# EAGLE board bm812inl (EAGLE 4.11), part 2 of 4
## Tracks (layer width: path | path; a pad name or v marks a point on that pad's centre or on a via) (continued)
D03MA4L  (via drill 0.61) (continued)
  Bottom 0.254: v102.91,115.24 102.59,115.56 98.46,115.56 97.83,116.19 88.94,116.19 88.3,115.56 82.59,115.56 81.63,114.61 C15.L1 | 104.81,195.57 95.29,195.57 94.33,196.52 B14.D1 | 104.81,195.57 105.76,196.52 B13.D1 | 117.51,195.57 118.46,196.52 B12.D1 | 104.81,195.57 117.51,195.57 | 130.21,195.57 131.16,196.52 B11.D1 | 117.51,195.57 130.21,195.57 | 142.91,195.57 143.86,196.52 B10.D1 | 130.21,195.57 142.91,195.57 | 155.61,195.57 156.56,196.52 B09.D1 | 142.91,195.57 155.61,195.57 | 168.31,195.57 169.26,196.52 B08.D1 | 155.61,195.57 168.31,195.57 | 181.01,195.57 181.96,196.52 B07.D1 | 168.31,195.57 181.01,195.57 | 193.71,195.57 194.66,196.52 B06.D1 | 181.01,195.57 193.71,195.57 | 206.41,195.57 207.36,196.52 B05.D1 | 193.71,195.57 206.41,195.57 | 219.11,195.57 220.06,196.52 B04.D1 | 206.41,195.57 219.11,195.57 | 231.81,195.57 232.76,196.52 B03.D1 | 219.11,195.57 231.81,195.57 | 244.51,195.57 245.46,196.52 B02.D1 | 231.81,195.57 244.51,195.57 | 244.51,195.57 257.21,195.57 258.16,196.52 B01.D1
D03MA5L  (via drill 0.61)
  Top 0.254: v102.91,96.19 105.13,98.41 105.13,187.31 109.26,191.44 109.26,193.03 B13.E1
  Bottom 0.254: v102.91,96.19 102.59,96.51 98.46,96.51 97.83,97.14 85.76,97.14 84.81,98.1 C15.S1 | 107.99,192.39 98.46,192.39 97.51,193.34 B14.E1 | 107.99,192.39 108.94,193.34 B13.E1 | 120.69,192.39 121.64,193.34 B12.E1 | 107.99,192.39 120.69,192.39 | 133.39,192.39 134.34,193.34 B11.E1 | 120.69,192.39 133.39,192.39 | 146.09,192.39 147.04,193.34 B10.E1 | 133.39,192.39 146.09,192.39 | 158.79,192.39 159.74,193.34 B09.E1 | 146.09,192.39 158.79,192.39 | 171.49,192.39 172.44,193.34 B08.E1 | 158.79,192.39 171.49,192.39 | 184.19,192.39 185.14,193.34 B07.E1 | 171.49,192.39 184.19,192.39 | 196.89,192.39 197.84,193.34 B06.E1 | 184.19,192.39 196.89,192.39 | 209.59,192.39 210.54,193.34 B05.E1 | 196.89,192.39 209.59,192.39 | 222.29,192.39 223.24,193.34 B04.E1 | 209.59,192.39 222.29,192.39 | 234.99,192.39 235.94,193.34 B03.E1 | 222.29,192.39 234.99,192.39 | 247.69,192.39 248.64,193.34 B02.E1 | 234.99,192.39 247.69,192.39 | 247.69,192.39 260.39,192.39 261.34,193.34 B01.E1
D03MA6L  (via drill 0.61)
  Top 0.254: v93.38,124.13 94.97,125.72 94.97,185.09 96.56,186.68 B14.H1
  Bottom 0.254: v93.38,124.13 91.79,122.54 76.87,122.54 75.28,120.96 C15.J2 | 111.16,186.04 110.21,186.99 B13.H1 | 111.16,186.04 120.69,186.04 | 120.69,186.04 121.64,186.99 B12.H1 | 133.39,186.04 134.34,186.99 B11.H1 | 120.69,186.04 133.39,186.04 | 146.09,186.04 147.04,186.99 B10.H1 | 133.39,186.04 146.09,186.04 | 158.79,186.04 159.74,186.99 B09.H1 | 146.09,186.04 158.79,186.04 | 171.49,186.04 172.44,186.99 B08.H1 | 158.79,186.04 171.49,186.04 | 184.19,186.04 185.14,186.99 B07.H1 | 171.49,186.04 184.19,186.04 | 196.89,186.04 197.84,186.99 B06.H1 | 184.19,186.04 196.89,186.04 | 209.59,186.04 210.54,186.99 B05.H1 | 196.89,186.04 209.59,186.04 | 222.29,186.04 223.24,186.99 B04.H1 | 209.59,186.04 222.29,186.04 | 234.99,186.04 235.94,186.99 B03.H1 | 222.29,186.04 234.99,186.04 | 247.69,186.04 248.64,186.99 B02.H1 | 234.99,186.04 247.69,186.04 | 247.69,186.04 260.39,186.04 261.34,186.99 B01.H1 | 111.16,186.04 102.59,186.04 101.95,186.68 97.83,186.68 97.51,186.99 B14.H1
D03MA7L  (via drill 0.61)
  Top 0.254: v88.62,106.03 88.62,170.17 92.43,173.98 92.43,182.55 93.38,183.5 B14.J1
  Bottom 0.254: v88.62,106.03 79.41,106.03 78.46,105.08 C15.P2 | 104.81,182.87 105.76,183.82 B13.J1 | 104.81,182.87 95.29,182.87 94.33,183.82 B14.J1 | 117.51,182.87 118.46,183.82 B12.J1 | 104.81,182.87 117.51,182.87 | 130.21,182.87 131.16,183.82 B11.J1 | 117.51,182.87 130.21,182.87 | 142.91,182.87 143.86,183.82 B10.J1 | 130.21,182.87 142.91,182.87 | 155.61,182.87 156.56,183.82 B09.J1 | 142.91,182.87 155.61,182.87 | 168.31,182.87 169.26,183.82 B08.J1 | 155.61,182.87 168.31,182.87 | 181.01,182.87 181.96,183.82 B07.J1 | 168.31,182.87 181.01,182.87 | 193.71,182.87 194.66,183.82 B06.J1 | 181.01,182.87 193.71,182.87 | 206.41,182.87 207.36,183.82 B05.J1 | 193.71,182.87 206.41,182.87 | 219.11,182.87 220.06,183.82 B04.J1 | 206.41,182.87 219.11,182.87 | 231.81,182.87 232.76,183.82 B03.J1 | 219.11,182.87 231.81,182.87 | 244.51,182.87 245.46,183.82 B02.J1 | 231.81,182.87 244.51,182.87 | 244.51,182.87 257.21,182.87 258.16,183.82 B01.J1
D03MA8L  (via drill 0.61)
  Top 0.254: v90.21,87.3 91.79,85.71 91.79,65.71 93.38,64.12 D14.D1
  Bottom 0.254: 104.81,62.22 95.29,62.22 94.33,63.17 D14.D1 | 104.81,62.22 105.76,63.17 D13.D1 | 117.51,62.22 118.46,63.17 D12.D1 | 117.51,62.22 104.81,62.22 | 130.21,62.22 131.16,63.17 D11.D1 | 130.21,62.22 117.51,62.22 | 142.91,62.22 143.86,63.17 D10.D1 | 142.91,62.22 130.21,62.22 | 155.61,62.22 156.56,63.17 D09.D1 | 155.61,62.22 142.91,62.22 | 168.31,62.22 169.26,63.17 D08.D1 | 168.31,62.22 155.61,62.22 | 181.01,62.22 181.96,63.17 D07.D1 | 181.01,62.22 168.31,62.22 | 193.71,62.22 194.66,63.17 D06.D1 | 193.71,62.22 181.01,62.22 | 206.41,62.22 207.36,63.17 D05.D1 | 193.71,62.22 206.41,62.22 | 219.11,62.22 220.06,63.17 D04.D1 | 206.41,62.22 219.11,62.22 | 231.81,62.22 232.76,63.17 D03.D1 | 219.11,62.22 231.81,62.22 | 244.51,62.22 245.46,63.17 D02.D1 | 231.81,62.22 244.51,62.22 | 244.51,62.22 257.21,62.22 258.16,63.17 D01.D1 | v90.21,87.3 76.55,87.3 75.28,88.57 C15.V2
D03MA9L  (via drill 0.61)
  Top 0.254: v96.56,127.62 98.14,126.03 98.14,61.9 97.19,60.95 D14.E1
  Bottom 0.254: 107.99,59.04 98.46,59.04 97.51,60 D14.E1 | 107.99,59.04 108.94,60 D13.E1 | 120.69,59.04 121.64,60 D12.E1 | 120.69,59.04 107.99,59.04 | 133.39,59.04 134.34,60 D11.E1 | 133.39,59.04 120.69,59.04 | 146.09,59.04 147.04,60 D10.E1 | 146.09,59.04 133.39,59.04 | 158.79,59.04 159.74,60 D09.E1 | 158.79,59.04 146.09,59.04 | 171.49,59.04 172.44,60 D08.E1 | 171.49,59.04 158.79,59.04 | 184.19,59.04 185.14,60 D07.E1 | 184.19,59.04 171.49,59.04 | 196.89,59.04 197.84,60 D06.E1 | 196.89,59.04 184.19,59.04 | 209.59,59.04 210.54,60 D05.E1 | 196.89,59.04 209.59,59.04 | 222.29,59.04 223.24,60 D04.E1 | 209.59,59.04 222.29,59.04 | 234.99,59.04 235.94,60 D03.E1 | 222.29,59.04 234.99,59.04 | 247.69,59.04 248.64,60 D02.E1 | 234.99,59.04 247.69,59.04 | 247.69,59.04 260.39,59.04 261.34,60 D01.E1 | v96.56,127.62 95.92,128.26 73.7,128.26 72.11,129.84 C16.E1
D03MA10L  (via drill 0.61)
  Top 0.254: v92.75,112.38 94.97,110.16 94.97,64.76 95.6,64.12 95.6,55.55 96.56,54.6 D14.H1
  Bottom 0.254: 107.99,52.69 98.46,52.69 97.51,53.64 D14.H1 | 107.99,52.69 108.94,53.64 D13.H1 | 120.69,52.69 121.64,53.64 D12.H1 | 120.69,52.69 107.99,52.69 | 133.39,52.69 134.34,53.64 D11.H1 | 133.39,52.69 120.69,52.69 | 146.09,52.69 147.04,53.64 D10.H1 | 146.09,52.69 133.39,52.69 | 158.79,52.69 159.74,53.64 D09.H1 | 158.79,52.69 146.09,52.69 | 171.49,52.69 172.44,53.64 D08.H1 | 171.49,52.69 158.79,52.69 | 184.19,52.69 185.14,53.64 D07.H1 | 184.19,52.69 171.49,52.69 | 196.89,52.69 197.84,53.64 D06.H1 | 196.89,52.69 184.19,52.69 | 209.59,52.69 210.54,53.64 D05.H1 | 209.59,52.69 196.89,52.69 | 222.29,52.69 223.24,53.64 D04.H1 | 209.59,52.69 222.29,52.69 | 234.99,52.69 235.94,53.64 D03.H1 | 222.29,52.69 234.99,52.69 | 247.69,52.69 248.64,53.64 D02.H1 | 234.99,52.69 247.69,52.69 | 247.69,52.69 260.39,52.69 261.34,53.64 D01.H1 | v92.75,112.38 70.52,112.38 68.93,113.97 C16.L1
D03MA11L  (via drill 0.61)
  Top 0.254: v89.57,95.87 92.43,93.02 92.43,66.66 94.97,64.12 94.97,52.38 94.02,51.42 D14.J1
  Bottom 0.254: 104.81,49.52 95.29,49.52 94.33,50.47 D14.J1 | 104.81,49.52 105.76,50.47 D13.J1 | 117.51,49.52 118.46,50.47 D12.J1 | 117.51,49.52 104.81,49.52 | 130.21,49.52 131.16,50.47 D11.J1 | 130.21,49.52 117.51,49.52 | 142.91,49.52 143.86,50.47 D10.J1 | 142.91,49.52 130.21,49.52 | 155.61,49.52 156.56,50.47 D09.J1 | 155.61,49.52 142.91,49.52 | 168.31,49.52 169.26,50.47 D08.J1 | 168.31,49.52 155.61,49.52 | 181.01,49.52 181.96,50.47 D07.J1 | 181.01,49.52 168.31,49.52 | 193.71,49.52 194.66,50.47 D06.J1 | 193.71,49.52 181.01,49.52 | 206.41,49.52 207.36,50.47 D05.J1 | 206.41,49.52 193.71,49.52 | 219.11,49.52 220.06,50.47 D04.J1 | 206.41,49.52 219.11,49.52 | 231.81,49.52 232.76,50.47 D03.J1 | 219.11,49.52 231.81,49.52 | 244.51,49.52 245.46,50.47 D02.J1 | 231.81,49.52 244.51,49.52 | 244.51,49.52 257.21,49.52 258.16,50.47 D01.J1 | v89.57,95.87 88.94,96.51 73.7,96.51 72.11,98.1 C16.S1
D03MCBMB0L
  Top 0.254: A19N.S2 27.34,231.13 28.93,229.54 28.93,227.32 33.37,222.87 B19.A1
D03MCBMB1L
  Top 0.254: B19.B1 29.56,203.51 28.29,204.77 28.29,222.24 24.17,226.36 24.17,227.95 A19N.T2
D03MCBMB2L
  Top 0.254: B19.F1 29.88,191.12 28.29,192.71 28.29,201.6 24.17,205.73 24.17,221.6 A19N.V2
D03MCBMB3L  (via drill 0.61)
  Top 0.254: v4.8,185.73 4.8,187.95 6.07,189.22 6.07,209.22 5.75,209.54 5.75,224.78 5.12,225.41 5.12,235.89 4.8,236.21 4.8,236.84 6.39,238.43 6.39,261.61 10.83,266.05 A20N.D2
  Bottom 0.254: v4.8,185.73 25.12,185.73 25.44,186.04 31.79,186.04 32.74,186.99 B19.H1
D03MCBMB4L  (via drill 0.61)
  Top 0.254: v42.26,213.35 42.26,204.46 41.31,203.51 41.31,199.7 40.36,198.74 40.36,196.2 32.1,187.95 32.1,180.33 32.74,179.69 32.74,175.56 33.06,175.25 B19.M1 | v27.34,216.21 26.39,217.16 26.39,222.87 v23.53,225.73 | v12.74,244.78 13.05,245.1 13.05,261.93 14.01,262.88 A20N.E2
  Bottom 0.254: v42.26,213.35 39.41,216.21 v27.34,216.21 | v23.53,225.73 21.94,227.32 6.39,227.32 5.12,228.59 5.12,237.8 5.75,237.8 v12.74,244.78
D03MCBMB5L  (via drill 0.61)
  Top 0.254: v5.43,255.26 5.12,254.94 5.12,237.8 4.16,236.84 4.16,236.21 4.48,235.89 4.48,218.11 5.12,217.48 5.12,209.54 5.43,209.22 5.43,189.22 3.85,187.63 3.85,173.66 v4.48,173.02
  Bottom 0.254: v5.43,255.26 12.1,255.26 13.69,256.85 A20N.H2 | v4.48,173.02 4.8,172.71 28.61,172.71 29.56,171.76 B19.N1
D03MCBMB6L  (via drill 0.61)
  Top 0.254: v33.69,198.43 35.28,200.01 35.28,217.16 37.18,219.06 37.18,220.97 37.82,221.6 37.82,248.59 39.41,250.18 A18N.K2
  Bottom 0.254: v33.69,198.43 25.75,198.43 24.48,197.15 B19.D2
D03MCBMB7L  (via drill 0.61)
  Top 0.254: v34.64,194.93 35.28,195.57 35.28,199.38 37.82,201.92 37.82,220.97 38.45,221.6 38.45,242.87 39.41,243.83 A18N.M2
  Bottom 0.254: v34.64,194.93 28.61,194.93 27.66,193.98 B19.E2
D03MCBMB8L  (via drill 0.61)
  Top 0.254: v42.58,181.28 44.17,182.87 44.17,241.92 43.53,242.56 40.04,242.56 40.04,238.75 A18N.P2
  Bottom 0.254: v42.58,181.28 40.99,179.69 28.61,179.69 27.66,180.64 B19.K2
D03MCBMB9L  (via drill 0.61)
  Top 0.254: v35.28,231.45 35.28,225.41 34.01,224.14 34.01,217.79 34.64,217.16 34.64,204.46 31.47,201.28 31.47,189.85 25.75,184.14 25.75,180.01 24.17,178.42 B19.L2
  Bottom 0.254: v35.28,231.45 39.09,231.45 A18N.S2
D03MCBMB10L  (via drill 0.61)
  Top 0.254: v8.93,167.63 9.24,167.95 v9.24,209.86 | v34.96,218.11 35.28,218.43 35.28,224.78 36.23,225.73 36.23,227.95 A18N.T2
  Bottom 0.254: v8.93,167.63 11.15,167.63 12.1,166.68 16.23,166.68 16.55,166.36 22.26,166.36 23.21,165.4 B19.R2 | v9.24,209.86 9.56,209.54 19.4,209.54 27.98,218.11 v34.96,218.11
D03MCBMB11L  (via drill 0.61)
  Top 0.254: v22.26,162.23 21.94,162.55 21.94,208.9 22.9,209.86 22.9,220.65 v22.26,221.29
  Bottom 0.254: v22.26,162.23 26.39,162.23 B19.S2 | v22.26,221.29 22.58,220.97 34.96,220.97 35.91,221.92 A18N.V2
D03MEMSTART  (via drill 0.61)
  Top 0.254: 48.3,43.17 48.93,43.8 D17.L2 49.57,45.07 51.15,46.66 51.15,69.52 54.96,69.52 D17.B1 | 48.3,43.17 47.98,42.85 47.98,37.45 50.52,34.91 50.52,30.78 52.11,29.2 D17.S2 | 48.3,43.17 44.17,47.29 44.17,55.55 43.22,56.5 D18.F1 | v87.03,245.73 88.3,244.46 v88.3,243.51 | v153.07,241.92 159.1,235.89 159.1,224.78 159.42,224.46 159.42,207.31 158.79,206.68 158.79,75.87 v119.42,36.5
  Bottom 0.254: D17.N1 54.96,38.4 53.38,39.99 51.79,39.99 49.57,42.21 49.57,43.8 D17.L2 | v87.03,245.73 66.71,245.73 65.76,244.78 A16.M2 | v88.3,243.51 89.25,242.56 152.44,242.56 v153.07,241.92 | v119.42,36.5 119.1,36.82 77.19,36.82 70.2,29.83 58.14,29.83 57.19,28.88 53.06,28.88 D17.S2
D04MD0L  (via drill 0.61)
  Top 0.254: v82.9,75.55 82.9,68.25 83.86,67.3 D15.C1 | v4.48,87.3 4.8,87.62 4.8,172.07 5.43,172.71 5.43,181.28 v4.8,181.92 | v94.97,218.11 94.97,238.75 95.6,239.38 95.6,249.23 96.56,250.18 A14.K1 | v32.42,211.12 31.47,210.17 31.47,201.92 30.52,200.96 30.52,197.47 B19.D1
  Bottom 0.254: 107.99,249.54 98.46,249.54 97.51,250.49 A14.K1 | 107.99,249.54 108.94,250.49 A13.K1 | 120.69,249.54 121.64,250.49 A12.K1 | 120.69,249.54 107.99,249.54 | 133.39,249.54 134.34,250.49 A11.K1 | 133.39,249.54 120.69,249.54 | 146.09,249.54 147.04,250.49 A10.K1 | 146.09,249.54 133.39,249.54 | 158.79,249.54 159.74,250.49 A09.K1 | 158.79,249.54 146.09,249.54 | 171.49,249.54 172.44,250.49 A08.K1 | 171.49,249.54 158.79,249.54 | 184.19,249.54 185.14,250.49 A07.K1 | 184.19,249.54 171.49,249.54 | 196.89,249.54 197.84,250.49 A06.K1 | 196.89,249.54 184.19,249.54 | 209.59,249.54 210.54,250.49 A05.K1 | 209.59,249.54 196.89,249.54 | 222.29,249.54 223.24,250.49 A04.K1 | 222.29,249.54 209.59,249.54 | 234.99,249.54 235.94,250.49 A03.K1 | 234.99,249.54 222.29,249.54 | 247.69,249.54 248.64,250.49 A02.K1 | 247.69,249.54 234.99,249.54 | 247.69,249.54 260.39,249.54 261.34,250.49 A01.K1 | v82.9,75.55 82.27,76.19 15.59,76.19 v4.48,87.3 | v4.8,181.92 4.8,183.18 3.21,184.77 3.21,195.57 27.98,195.57 28.93,196.52 29.56,196.52 B19.D1 | v94.97,218.11 92.75,215.89 76.55,215.89 70.2,209.54 48.93,209.54 47.34,211.12 v32.42,211.12
D04MD1L  (via drill 0.61)
  Top 0.254: v80.05,75.24 82.27,73.01 82.27,60.63 78.46,60.63 D15.E2 | v5.43,75.55 5.43,172.07 6.07,172.71 6.07,181.92 5.43,182.55 5.43,185.09 5.75,185.41 v5.75,187.63 | v91.79,208.9 91.79,245.42 93.38,247 A14.L1 | v40.36,210.17 38.45,208.27 38.45,196.84 35.6,193.98 34.01,193.98 B19.E1
  Bottom 0.254: 104.81,246.37 95.29,246.37 94.33,247.32 A14.L1 | 104.81,246.37 105.76,247.32 A13.L1 | 117.51,246.37 118.46,247.32 A12.L1 | 104.81,246.37 117.51,246.37 | 130.21,246.37 131.16,247.32 A11.L1 | 117.51,246.37 130.21,246.37 | 142.91,246.37 143.86,247.32 A10.L1 | 130.21,246.37 142.91,246.37 | 155.61,246.37 156.56,247.32 A09.L1 | 142.91,246.37 155.61,246.37 | 168.31,246.37 169.26,247.32 A08.L1 | 155.61,246.37 168.31,246.37 | 181.01,246.37 181.96,247.32 A07.L1 | 168.31,246.37 181.01,246.37 | 193.71,246.37 194.66,247.32 A06.L1 | 181.01,246.37 193.71,246.37 | 206.41,246.37 207.36,247.32 A05.L1 | 193.71,246.37 206.41,246.37 | 219.11,246.37 220.06,247.32 A04.L1 | 206.41,246.37 219.11,246.37 | 231.81,246.37 232.76,247.32 A03.L1 | 219.11,246.37 231.81,246.37 | 244.51,246.37 245.46,247.32 A02.L1 | 231.81,246.37 244.51,246.37 | 244.51,246.37 257.21,246.37 258.16,247.32 A01.L1 | v80.05,75.24 79.73,75.55 v5.43,75.55 | v5.75,187.63 9.88,191.76 28.29,191.76 30.2,193.66 B19.E1 | v91.79,208.9 48.93,208.9 47.66,210.17 v40.36,210.17
D04MD2L  (via drill 0.61)
  Top 0.254: v6.7,71.74 6.39,72.06 6.39,75.87 6.07,76.19 6.07,163.18 8.29,165.4 8.29,166.99 7.97,167.31 7.97,173.34 v8.29,173.66 | v33.69,178.11 33.69,180.33 B19.K1 33.69,181.6 34.64,182.55 34.64,189.22 v34.96,189.54 | v93.06,192.08 94.97,193.98 94.97,206.36 95.92,207.31 95.92,218.43 95.6,218.74 95.6,238.75 96.24,239.38 96.24,243.51 96.56,243.83 A14.M1
  Bottom 0.254: 107.99,243.19 98.46,243.19 97.51,244.14 A14.M1 | 107.99,243.19 108.94,244.14 A13.M1 | 120.69,243.19 121.64,244.14 A12.M1 | 107.99,243.19 120.69,243.19 | 133.39,243.19 134.34,244.14 A11.M1 | 120.69,243.19 133.39,243.19 | 146.09,243.19 147.04,244.14 A10.M1 | 133.39,243.19 146.09,243.19 | 158.79,243.19 159.74,244.14 A09.M1 | 146.09,243.19 158.79,243.19 | 171.49,243.19 172.44,244.14 A08.M1 | 158.79,243.19 171.49,243.19 | 184.19,243.19 185.14,244.14 A07.M1 | 171.49,243.19 184.19,243.19 | 196.89,243.19 197.84,244.14 A06.M1 | 184.19,243.19 196.89,243.19 | 209.59,243.19 210.54,244.14 A05.M1 | 196.89,243.19 209.59,243.19 | 222.29,243.19 223.24,244.14 A04.M1 | 209.59,243.19 222.29,243.19 | 234.99,243.19 235.94,244.14 A03.M1 | 222.29,243.19 234.99,243.19 | 247.69,243.19 248.64,244.14 A02.M1 | 234.99,243.19 247.69,243.19 | 247.69,243.19 260.39,243.19 261.34,244.14 A01.M1 | v6.7,71.74 29.56,48.88 43.53,48.88 46.71,52.06 79.41,52.06 80.36,51.1 D15.J1 | v8.29,173.66 8.61,173.34 28.93,173.34 v33.69,178.11 | v93.06,192.08 92.75,191.76 84.17,191.76 81.63,189.22 35.28,189.22 v34.96,189.54
D04MD3L  (via drill 0.61)
  Top 0.254: v3.21,173.02 3.21,195.89 4.8,197.47 4.8,209.22 4.16,209.86 v4.16,217.16 | v96.56,220.02 98.14,221.6 98.14,236.52 97.19,237.48 A14.P1 | v132.12,145.08 132.12,143.81 129.89,141.59 129.89,76.19 92.43,38.72 92.43,30.47 85.44,30.47 82.27,33.64 82.27,40.95 78.46,40.95 D15.M2 | v146.72,150.17 146.4,150.48 146.4,236.52 147.36,237.48 A10.P1
  Bottom 0.254: v3.21,173.02 6.07,175.88 24.48,175.88 26.07,177.47 29.56,177.47 B19.L1 | v4.16,217.16 10.51,223.51 52.42,223.51 55.6,220.33 96.24,220.33 v96.56,220.02 | 107.99,236.84 108.94,237.8 A13.P1 | 107.99,236.84 98.46,236.84 97.51,237.8 A14.P1 | 120.69,236.84 121.64,237.8 A12.P1 | 120.69,236.84 107.99,236.84 | 120.69,236.84 133.39,236.84 134.34,237.8 A11.P1 135.61,237.8 136.56,236.84 149.26,236.84 | v132.12,145.08 137.2,150.17 v146.72,150.17 | 158.79,236.84 159.74,237.8 A09.P1 | 149.26,236.84 158.79,236.84 | 149.26,236.84 148.31,237.8 A10.P1 | 171.49,236.84 172.44,237.8 A08.P1 | 158.79,236.84 171.49,236.84 | 184.19,236.84 185.14,237.8 A07.P1 | 171.49,236.84 184.19,236.84 | 196.89,236.84 197.84,237.8 A06.P1 | 184.19,236.84 196.89,236.84 | 209.59,236.84 210.54,237.8 A05.P1 | 196.89,236.84 209.59,236.84 | 222.29,236.84 223.24,237.8 A04.P1 | 209.59,236.84 222.29,236.84 | 234.99,236.84 235.94,237.8 A03.P1 | 222.29,236.84 234.99,236.84 | 247.69,236.84 248.64,237.8 A02.P1 | 234.99,236.84 247.69,236.84 | 247.69,236.84 260.39,236.84 261.34,237.8 A01.P1
D04MD4L  (via drill 0.61)
  Top 0.254: v85.44,179.06 85.44,88.25 85.76,87.94 85.76,74.28 85.44,73.97 85.44,36.5 84.49,35.55 D15.P1
  Bottom 0.254: 95.29,179.69 86.08,179.69 v85.44,179.06 67.66,179.06 64.49,175.88 44.8,175.88 35.91,166.99 32.42,166.99 30.83,165.4 B19.R1 | 95.29,179.69 96.24,180.64 B14.K1 | 107.99,179.69 108.94,180.64 B13.K1 | 95.29,179.69 107.99,179.69 | 120.69,179.69 121.64,180.64 B12.K1 | 107.99,179.69 120.69,179.69 | 133.39,179.69 134.34,180.64 B11.K1 | 120.69,179.69 133.39,179.69 | 146.09,179.69 147.04,180.64 B10.K1 | 133.39,179.69 146.09,179.69 | 158.79,179.69 159.74,180.64 B09.K1 | 146.09,179.69 158.79,179.69 | 171.49,179.69 172.44,180.64 B08.K1 | 158.79,179.69 171.49,179.69 | 184.19,179.69 185.14,180.64 B07.K1 | 171.49,179.69 184.19,179.69 | 196.89,179.69 197.84,180.64 B06.K1 | 184.19,179.69 196.89,179.69 | 209.59,179.69 210.54,180.64 B05.K1 | 196.89,179.69 209.59,179.69 | 222.29,179.69 223.24,180.64 B04.K1 | 209.59,179.69 222.29,179.69 | 234.99,179.69 235.94,180.64 B03.K1 | 222.29,179.69 234.99,179.69 | 247.69,179.69 248.64,180.64 B02.K1 | 234.99,179.69 247.69,179.69 | 247.69,179.69 260.39,179.69 261.34,180.64 B01.K1
D04MD5L  (via drill 0.61)
  Top 0.254: v85.13,32.69 88.62,36.18 88.62,100.95 91.79,104.13 91.79,150.48 | 91.79,150.48 91.79,172.71 93.38,174.3 93.38,177.15 B14.L1 | v34.96,152.07 34.96,155.88 34.01,156.83 34.01,160.96 33.69,161.28 B19.S1 | 91.79,150.48 v92.11,150.48
  Bottom 0.254: v85.13,32.69 79.09,26.66 76.24,26.66 75.28,25.71 D15.T2 | v34.96,152.07 35.91,151.12 46.07,151.12 48.61,153.66 69.89,153.66 73.06,150.48 v92.11,150.48 | 104.81,176.52 105.76,177.47 B13.L1 | 104.81,176.52 95.29,176.52 94.33,177.47 B14.L1 | 117.51,176.52 118.46,177.47 B12.L1 | 104.81,176.52 117.51,176.52 | 130.21,176.52 131.16,177.47 B11.L1 | 117.51,176.52 130.21,176.52 | 142.91,176.52 143.86,177.47 B10.L1 | 130.21,176.52 142.91,176.52 | 155.61,176.52 156.56,177.47 B09.L1 | 142.91,176.52 155.61,176.52 | 168.31,176.52 169.26,177.47 B08.L1 | 155.61,176.52 168.31,176.52 | 181.01,176.52 181.96,177.47 B07.L1 | 168.31,176.52 181.01,176.52 | 193.71,176.52 194.66,177.47 B06.L1 | 181.01,176.52 193.71,176.52 | 206.41,176.52 207.36,177.47 B05.L1 | 193.71,176.52 206.41,176.52 | 219.11,176.52 220.06,177.47 B04.L1 | 206.41,176.52 219.11,176.52 | 231.81,176.52 232.76,177.47 B03.L1 | 219.11,176.52 231.81,176.52 | 244.51,176.52 245.46,177.47 B02.L1 | 231.81,176.52 244.51,176.52 | 244.51,176.52 257.21,176.52 258.16,177.47 B01.L1
D04MD6L  (via drill 0.61)
  Top 0.254: v95.92,68.25 95.6,68.57 95.6,74.28 95.92,74.6 95.92,91.11 95.6,91.43 95.6,173.02 96.56,173.98 B14.M1 97.19,175.25 98.14,176.2 98.14,189.22 v95.6,189.22
  Bottom 0.254: v95.92,68.25 95.29,67.61 92.75,67.61 92.43,67.93 73.06,67.93 72.11,66.98 D16.C1 | v95.6,189.22 92.11,189.22 91.48,188.58 28.61,188.58 27.66,187.63 B19.H2 | 107.99,173.34 108.94,174.3 B13.M1 | 107.99,173.34 98.46,173.34 97.51,174.3 B14.M1 | 120.69,173.34 121.64,174.3 B12.M1 | 107.99,173.34 120.69,173.34 | 133.39,173.34 134.34,174.3 B11.M1 | 120.69,173.34 133.39,173.34 | 146.09,173.34 147.04,174.3 B10.M1 | 133.39,173.34 146.09,173.34 | 158.79,173.34 159.74,174.3 B09.M1 | 146.09,173.34 158.79,173.34 | 171.49,173.34 172.44,174.3 B08.M1 | 158.79,173.34 171.49,173.34 | 184.19,173.34 185.14,174.3 B07.M1 | 171.49,173.34 184.19,173.34 | 196.89,173.34 197.84,174.3 B06.M1 | 184.19,173.34 196.89,173.34 | 209.59,173.34 210.54,174.3 B05.M1 | 196.89,173.34 209.59,173.34 | 222.29,173.34 223.24,174.3 B04.M1 | 209.59,173.34 222.29,173.34 | 234.99,173.34 235.94,174.3 B03.M1 | 222.29,173.34 234.99,173.34 | 247.69,173.34 248.64,174.3 B02.M1 | 234.99,173.34 247.69,173.34 | 247.69,173.34 260.39,173.34 261.34,174.3 B01.M1
D04MD7L  (via drill 0.61)
  Top 0.254: v65.44,55.55 65.44,59.68 D16.E2 | v102.91,55.87 111.48,64.44 111.48,166.04 109.89,167.63 B13.P1 | v84.81,185.41 86.08,184.14 86.08,179.69 86.4,179.37 86.4,178.74 86.08,178.42 86.08,169.21 v87.67,167.63
  Bottom 0.254: v65.44,55.55 65.76,55.23 95.6,55.23 96.24,55.87 v102.91,55.87 | 98.46,166.99 97.51,167.95 B14.P1 | 98.46,166.99 107.99,166.99 | 107.99,166.99 108.94,167.95 B13.P1 | 120.69,166.99 121.64,167.95 B12.P1 | 107.99,166.99 120.69,166.99 | v84.81,185.41 71.47,185.41 70.52,186.36 67.03,186.36 66.08,185.41 25.44,185.41 24.48,184.46 B19.J2 | v87.67,167.63 88.3,166.99 98.46,166.99 | 133.39,166.99 134.34,167.95 B11.P1 | 120.69,166.99 133.39,166.99 | 146.09,166.99 147.04,167.95 B10.P1 | 133.39,166.99 146.09,166.99 | 158.79,166.99 159.74,167.95 B09.P1 | 146.09,166.99 158.79,166.99 | 171.49,166.99 172.44,167.95 B08.P1 | 158.79,166.99 171.49,166.99 | 184.19,166.99 185.14,167.95 B07.P1 | 171.49,166.99 184.19,166.99 | 196.89,166.99 197.84,167.95 B06.P1 | 184.19,166.99 196.89,166.99 | 209.59,166.99 210.54,167.95 B05.P1 | 196.89,166.99 209.59,166.99 | 222.29,166.99 223.24,167.95 B04.P1 | 209.59,166.99 222.29,166.99 | 234.99,166.99 235.94,167.95 B03.P1 | 222.29,166.99 234.99,166.99 | 247.69,166.99 248.64,167.95 B02.P1 | 234.99,166.99 247.69,166.99 | 247.69,166.99 260.39,166.99 261.34,167.95 B01.P1
D04MD8L  (via drill 0.61)
  Top 0.254: v20.99,94.92 9.88,106.03 9.88,116.83 19.4,126.35 19.4,150.48 25.12,156.2 25.12,165.72 24.48,166.36 24.48,170.49 24.17,170.8 B19.N2 | v89.57,90.16 89.25,89.84 89.25,53.33 94.65,47.93 96.24,47.93 D14.K1
  Bottom 0.254: 107.99,48.88 98.46,48.88 97.51,47.93 D14.K1 96.24,47.93 94.65,49.52 69.89,49.52 68.93,50.47 D16.J1 | 107.99,48.88 108.94,47.93 D13.K1 | v20.99,94.92 28.29,87.62 71.47,87.62 74.01,90.16 v89.57,90.16 | 120.69,48.88 121.64,47.93 D12.K1 | 120.69,48.88 107.99,48.88 | 133.39,48.88 134.34,47.93 D11.K1 | 133.39,48.88 120.69,48.88 | 146.09,48.88 147.04,47.93 D10.K1 | 146.09,48.88 133.39,48.88 | 158.79,48.88 159.74,47.93 D09.K1 | 158.79,48.88 146.09,48.88 | 171.49,48.88 172.44,47.93 D08.K1 | 171.49,48.88 158.79,48.88 | 184.19,48.88 185.14,47.93 D07.K1 | 184.19,48.88 171.49,48.88 | 196.89,48.88 197.84,47.93 D06.K1 | 196.89,48.88 184.19,48.88 | 209.59,48.88 210.54,47.93 D05.K1 | 209.59,48.88 196.89,48.88 | 222.29,48.88 223.24,47.93 D04.K1 | 209.59,48.88 222.29,48.88 | 234.99,48.88 235.94,47.93 D03.K1 | 222.29,48.88 234.99,48.88 | 247.69,48.88 248.64,47.93 D02.K1 | 234.99,48.88 247.69,48.88 | 247.69,48.88 260.39,48.88 261.34,47.93 D01.K1
D04MD9L  (via drill 0.61)
  Top 0.254: v22.58,142.86 22.58,153.02 25.75,156.2 25.75,166.68 26.71,167.63 B19.P2 | v22.9,135.88 22.58,135.56 22.58,82.22 22.9,81.9 22.9,70.79 22.58,70.47 22.58,55.55 v35.91,42.21
  Bottom 0.254: v22.58,142.86 22.58,135.88 v22.9,135.88 | v35.91,42.21 38.77,39.36 52.42,39.36 54.96,36.82 58.77,36.82 62.9,40.95 64.49,40.95 D16.M2 65.76,41.58 67.35,43.17 92.11,43.17 93.06,44.12 D14.L1 94.33,44.12 95.29,43.17 104.81,43.17 | 104.81,43.17 105.76,44.12 D13.L1 | 117.51,43.17 118.46,44.12 D12.L1 | 117.51,43.17 104.81,43.17 | 130.21,43.17 131.16,44.12 D11.L1 | 130.21,43.17 117.51,43.17 | 142.91,43.17 143.86,44.12 D10.L1 | 142.91,43.17 130.21,43.17 | 155.61,43.17 156.56,44.12 D09.L1 | 155.61,43.17 142.91,43.17 | 168.31,43.17 169.26,44.12 D08.L1 | 168.31,43.17 155.61,43.17 | 181.01,43.17 181.96,44.12 D07.L1 | 181.01,43.17 168.31,43.17 | 193.71,43.17 194.66,44.12 D06.L1 | 193.71,43.17 181.01,43.17 | 206.41,43.17 207.36,44.12 D05.L1 | 206.41,43.17 193.71,43.17 | 219.11,43.17 220.06,44.12 D04.L1 | 219.11,43.17 206.41,43.17 | 231.81,43.17 232.76,44.12 D03.L1 | 219.11,43.17 231.81,43.17 | 244.51,43.17 245.46,44.12 D02.L1 | 231.81,43.17 244.51,43.17 | 244.51,43.17 257.21,43.17 258.16,44.12 D01.L1
D04MD10L  (via drill 0.61)
  Top 0.254: v21.94,50.79 21.94,70.47 22.26,70.79 22.26,81.9 21.94,82.22 21.94,139.69 25.12,142.86 25.12,153.34 26.71,154.93 B19.U2
  Bottom 0.254: 95.29,39.99 79.73,39.99 76.55,36.82 73.7,36.82 72.11,35.23 D16.P1 70.84,34.6 69.89,33.64 39.09,33.64 v21.94,50.79 | 95.29,39.99 96.24,40.95 D14.M1 | 107.99,39.99 108.94,40.95 D13.M1 | 107.99,39.99 95.29,39.99 | 120.69,39.99 121.64,40.95 D12.M1 | 120.69,39.99 107.99,39.99 | 133.39,39.99 134.34,40.95 D11.M1 | 133.39,39.99 120.69,39.99 | 146.09,39.99 147.04,40.95 D10.M1 | 146.09,39.99 133.39,39.99 | 158.79,39.99 159.74,40.95 D09.M1 | 158.79,39.99 146.09,39.99 | 171.49,39.99 172.44,40.95 D08.M1 | 171.49,39.99 158.79,39.99 | 184.19,39.99 185.14,40.95 D07.M1 | 184.19,39.99 171.49,39.99 | 196.89,39.99 197.84,40.95 D06.M1 | 196.89,39.99 184.19,39.99 | 209.59,39.99 210.54,40.95 D05.M1 | 209.59,39.99 196.89,39.99 | 222.29,39.99 223.24,40.95 D04.M1 | 222.29,39.99 209.59,39.99 | 234.99,39.99 235.94,40.95 D03.M1 | 222.29,39.99 234.99,39.99 | 247.69,39.99 248.64,40.95 D02.M1 | 234.99,39.99 247.69,39.99 | 247.69,39.99 260.39,39.99 261.34,40.95 D01.M1
D04MD11L  (via drill 0.61)
  Top 0.254: v2.58,149.53 2.89,149.21 2.89,76.19 5.12,73.97 5.12,52.38 v30.52,26.98
  Bottom 0.254: 63.54,26.66 64.17,27.29 78.46,27.29 84.81,33.64 95.29,33.64 | 63.54,26.66 62.58,25.71 D16.T2 | 95.29,33.64 96.24,34.6 D14.P1 | v2.58,149.53 7.66,154.61 12.42,154.61 15.91,151.12 22.26,151.12 23.21,152.07 B19.V2 | v30.52,26.98 30.83,26.66 63.54,26.66 | 107.99,33.64 108.94,34.6 D13.P1 | 107.99,33.64 95.29,33.64 | 120.69,33.64 121.64,34.6 D12.P1 | 120.69,33.64 107.99,33.64 | 133.39,33.64 134.34,34.6 D11.P1 | 133.39,33.64 120.69,33.64 | 146.09,33.64 147.04,34.6 D10.P1 | 146.09,33.64 133.39,33.64 | 158.79,33.64 159.74,34.6 D09.P1 | 158.79,33.64 146.09,33.64 | 171.49,33.64 172.44,34.6 D08.P1 | 171.49,33.64 158.79,33.64 | 184.19,33.64 185.14,34.6 D07.P1 | 184.19,33.64 171.49,33.64 | 196.89,33.64 197.84,34.6 D06.P1 | 196.89,33.64 184.19,33.64 | 209.59,33.64 210.54,34.6 D05.P1 | 209.59,33.64 196.89,33.64 | 222.29,33.64 223.24,34.6 D04.P1 | 222.29,33.64 209.59,33.64 | 234.99,33.64 235.94,34.6 D03.P1 | 222.29,33.64 234.99,33.64 | 247.69,33.64 248.64,34.6 D02.P1 | 234.99,33.64 247.69,33.64 | 247.69,33.64 260.39,33.64 261.34,34.6 D01.P1
GND
  Top 0.635: 101.64,240.97 100.68,240.97 A13.N2 | 101.64,240.97 105.76,240.97 A13.N1 | A11.N2 124.81,240.97 119.73,240.97 A12.N1 | A08.N2 164.18,240.97 169.26,240.97 A08.N1 170.53,240.97 175.61,240.97 A07.N2 176.88,240.97 181.96,240.97 A07.N1 183.23,240.97 188.31,240.97 A06.N2 189.58,240.97 194.66,240.97 A06.N1 195.93,240.97 201.01,240.97 A05.N2 202.28,240.97 207.36,240.97 A05.N1 208.63,240.97 213.71,240.97 A04.N2 | A03.N2 226.41,240.97 221.33,240.97 A04.N1 | A03.N1 234.03,240.97 239.11,240.97 A02.N2 240.38,240.97 245.46,240.97 A02.N1 246.73,240.97 251.81,240.97 A01.N2 253.08,240.97 258.16,240.97 A01.N1 | 101.64,228.27 100.68,228.27 A13.T2 | 101.64,228.27 105.76,228.27 A13.T1 | A11.T2 124.81,228.27 119.73,228.27 A12.T1 | A08.T2 164.18,228.27 169.26,228.27 A08.T1 170.53,228.27 175.61,228.27 A07.T2 176.88,228.27 181.01,228.27 | 181.01,228.27 181.96,228.27 A07.T1 183.23,228.27 188.31,228.27 A06.T2 189.58,228.27 194.66,228.27 A06.T1 195.93,228.27 201.01,228.27 A05.T2 202.28,228.27 207.36,228.27 A05.T1 208.63,228.27 213.71,228.27 A04.T2 | A03.T2 226.41,228.27 221.33,228.27 A04.T1 | A03.T1 234.03,228.27 239.11,228.27 A02.T2 240.38,228.27 245.46,228.27 A02.T1 246.73,228.27 251.81,228.27 A01.T2 253.08,228.27 258.16,228.27 A01.T1 | 101.64,228.27 101.64,240.97 | A14.F2 87.98,260.02 93.06,260.02 A14.F1 | A13.F1 105.76,260.02 100.68,260.02 A13.F2 | A11.F2 124.81,260.02 119.73,260.02 A12.F1 | A08.F2 164.18,260.02 169.26,260.02 A08.F1 170.53,260.02 175.61,260.02 A07.F2 176.88,260.02 181.96,260.02 A07.F1 183.23,260.02 188.31,260.02 A06.F2 189.58,260.02 194.66,260.02 A06.F1 195.93,260.02 201.01,260.02 A05.F2 202.28,260.02 207.36,260.02 A05.F1 208.63,260.02 213.71,260.02 A04.F2
  Top 0.635: A03.F2 226.41,260.02 221.33,260.02 A04.F1 | A03.F1 234.03,260.02 239.11,260.02 A02.F2 240.38,260.02 245.46,260.02 A02.F1 246.73,260.02 251.81,260.02 A01.F2 253.08,260.02 258.16,260.02 A01.F1 258.48,260.97 257.21,262.24 257.21,269.55 | A20N.C2 14.96,269.55 20.04,269.55 A20N.C1 | A20N.C1 21.31,269.55 26.39,269.55 A19N.C2 27.66,269.55 32.74,269.55 A19N.C1 33.06,270.5 33.06,275.58 A19N.A1 | A18N.C1 45.44,269.55 40.36,269.55 A18N.C2 | A18N.C1 46.71,269.55 51.79,269.55 A17N.C2 53.06,269.55 58.14,269.55 A17N.C1 | A17N.C1 59.41,269.55 64.49,269.55 A16.C2 65.76,269.55 69.89,269.55 | 69.89,269.55 70.84,269.55 A16.C1 | A15.C2 77.19,269.55 72.11,269.55 A16.C1 | A20N.A1 20.36,275.58 20.36,270.5 A20N.C1 | A18N.A1 45.76,275.58 45.76,270.5 A18N.C1 | A17N.A1 58.46,275.58 58.46,270.5 A17N.C1 | A16.A1 71.16,275.58 71.16,270.5 A16.C1 | A16.U2 65.76,225.73 67.98,227.95 A16.T1 67.98,229.22 67.98,234.3 A16.R1 67.98,235.57 67.98,240.65 A16.N1 | A17N.U2 53.06,225.73 55.28,227.95 A17N.T1 55.28,229.22 55.28,234.3 A17N.R1 55.28,235.57 55.28,240.65 A17N.N1 | A16.R2 61.63,235.57 61.63,240.65 A16.N2 61.63,241.92 61.63,247 A16.L2 61.31,247.96 59.09,250.18 A17N.K1 59.41,251.13 61.63,253.35 A16.J2 61.63,254.62 61.63,259.7 A16.F2 | A17N.L2 48.61,247.96 46.39,250.18 A18N.K1 46.71,251.13 48.93,253.35 A17N.J2 48.93,254.62 48.93,259.7 A17N.F2 49.88,260.02 54.96,260.02 A17N.F1 | 69.73,258.59 68.62,259.7 A16.F1 | 69.73,258.59 69.89,258.43 69.89,252.72 71.16,251.45 A16.K1 | A19N.R1 29.88,234.3 29.88,229.22 A19N.T1 | A19N.N1 29.88,240.65 29.88,235.57 A19N.R1 | A19N.R1 30.83,234.62 35.91,234.62 A18N.R2 36.23,235.57 36.23,240.65 A18N.N2 36.23,241.92 36.23,247 A18N.L2 35.91,247.96 33.69,250.18 A19N.K1 34.01,251.13 36.23,253.35 A18N.J2 36.23,254.62 36.23,259.7 A18N.F2 37.18,260.02 42.26,260.02 A18N.F1
  Top 0.635: A18N.U2 40.36,225.73 42.58,227.95 A18N.T1 42.58,229.22 42.58,234.3 A18N.R1 42.58,235.57 42.58,240.65 A18N.N1 | A17N.N2 48.93,240.65 48.93,235.57 A17N.R2 | A19N.F2 23.53,259.7 23.53,254.62 A19N.J2 23.53,253.35 23.53,248.27 A19N.L2 23.53,247 23.53,241.92 A19N.N2 23.53,240.65 23.53,235.57 A19N.R2 | A20N.U2 14.96,225.73 17.18,227.95 A20N.T1 17.18,229.22 17.18,234.3 A20N.R1 17.18,235.57 17.18,240.65 A20N.N1 | A20N.R2 10.83,235.57 10.83,240.65 A20N.N2 10.83,241.92 10.83,247 A20N.L2 10.83,248.27 10.83,253.35 A20N.J2 10.83,254.62 10.83,259.7 A20N.F2 | 69.89,269.55 69.89,258.75 69.73,258.59 | GND.1 267.37,269.55 262.61,269.55 A01.C1 261.34,269.55 257.21,269.55 | A14.C2 91.16,269.55 96.24,269.55 A14.C1 97.51,269.55 102.59,269.55 A13.C2 | A13.C1 110.21,269.55 115.29,269.55 A12.C2 116.56,269.55 121.64,269.55 A12.C1 122.91,269.55 127.99,269.55 A11.C2 | A09.C2 154.66,269.55 159.74,269.55 A09.C1 161.01,269.55 166.09,269.55 A08.C2 167.36,269.55 172.44,269.55 A08.C1 173.71,269.55 178.79,269.55 A07.C2 180.06,269.55 185.14,269.55 A07.C1 186.41,269.55 191.49,269.55 A06.C2 192.76,269.55 197.84,269.55 A06.C1 199.11,269.55 204.19,269.55 A05.C2 205.46,269.55 210.54,269.55 A05.C1 211.81,269.55 216.89,269.55 A04.C2 218.16,269.55 223.24,269.55 A04.C1 | A03.C1 237.21,269.55 242.29,269.55 A02.C2 243.56,269.55 248.64,269.55 A02.C1 249.91,269.55 254.99,269.55 A01.C2 256.26,269.55 257.21,269.55 | 165.14,171.12 164.18,171.12 B08.N2 | 165.14,171.12 169.26,171.12 B08.N1 170.53,171.12 175.61,171.12 B07.N2 176.88,171.12 181.96,171.12 B07.N1 | B06.N2 189.58,171.12 194.66,171.12 B06.N1 195.93,171.12 201.01,171.12 B05.N2 202.28,171.12 207.36,171.12 B05.N1 208.63,171.12 213.71,171.12 B04.N2 214.98,171.12 220.06,171.12 B04.N1 221.33,171.12 226.41,171.12 B03.N2 227.68,171.12 232.76,171.12 B03.N1 234.03,171.12 239.11,171.12 B02.N2 240.38,171.12 245.46,171.12 B02.N1
  Top 0.635: B01.N2 253.08,171.12 258.16,171.12 B01.N1 258.48,172.07 257.21,173.34 257.21,190.17 | 165.14,158.42 164.18,158.42 B08.T2 | 165.14,158.42 169.26,158.42 B08.T1 | 181.01,158.42 176.88,158.42 B07.T2 | 181.01,158.42 181.96,158.42 B07.T1 183.23,158.42 188.31,158.42 B06.T2 189.58,158.42 194.66,158.42 B06.T1 195.93,158.42 201.01,158.42 B05.T2 202.28,158.42 207.36,158.42 B05.T1 208.63,158.42 213.71,158.42 B04.T2 214.98,158.42 220.06,158.42 B04.T1 221.33,158.42 226.41,158.42 B03.T2 227.68,158.42 232.76,158.42 B03.T1 234.03,158.42 239.11,158.42 B02.T2 240.38,158.42 245.46,158.42 B02.T1 | B01.T1 258.16,158.42 253.08,158.42 B01.T2 | 165.14,158.42 165.14,171.12 | B13.F2 99.41,190.17 94.33,190.17 B14.F1 | B08.F2 164.18,190.17 169.26,190.17 B08.F1 170.53,190.17 175.61,190.17 B07.F2 176.88,190.17 181.96,190.17 B07.F1 183.23,190.17 188.31,190.17 B06.F2 189.58,190.17 194.66,190.17 B06.F1 195.93,190.17 201.01,190.17 B05.F2 | B05.F1 208.63,190.17 213.71,190.17 B04.F2 214.98,190.17 220.06,190.17 B04.F1 221.33,190.17 226.41,190.17 B03.F2 227.68,190.17 232.76,190.17 B03.F1 234.03,190.17 239.11,190.17 B02.F2 240.38,190.17 245.46,190.17 B02.F1 | 257.21,190.17 253.08,190.17 B01.F2 | 257.21,190.17 258.16,190.17 B01.F1 | 107.99,199.7 103.86,199.7 B13.C2 | 107.99,199.7 108.94,199.7 B13.C1 | B08.C2 167.36,199.7 172.44,199.7 B08.C1 173.71,199.7 178.79,199.7 B07.C2 180.06,199.7 181.01,199.7 | 181.01,199.7 185.14,199.7 B07.C1 186.41,199.7 191.49,199.7 B06.C2 192.76,199.7 197.84,199.7 B06.C1 199.11,199.7 204.19,199.7 B05.C2 205.46,199.7 210.54,199.7 B05.C1
  Top 0.635: B04.C2 218.16,199.7 223.24,199.7 B04.C1 224.51,199.7 229.59,199.7 B03.C2 230.86,199.7 235.94,199.7 B03.C1 237.21,199.7 242.29,199.7 B02.C2 243.56,199.7 248.64,199.7 B02.C1 | B01.C1 261.34,199.7 256.26,199.7 B01.C2 | 107.99,199.7 107.99,192.39 106.72,191.12 B13.F1 | D13.N2 99.41,37.77 94.33,37.77 D14.N1 | 133.39,37.77 132.43,37.77 D11.N1 | 133.39,37.77 137.51,37.77 D10.N2 138.78,37.77 143.86,37.77 D10.N1 145.13,37.77 150.21,37.77 D09.N2 151.48,37.77 156.56,37.77 D09.N1 157.83,37.77 162.91,37.77 D08.N2 164.18,37.77 169.26,37.77 D08.N1 170.53,37.77 175.61,37.77 D07.N2 176.88,37.77 181.96,37.77 D07.N1 183.23,37.77 188.31,37.77 D06.N2 189.58,37.77 194.66,37.77 D06.N1 195.93,37.77 201.01,37.77 D05.N2 202.28,37.77 207.36,37.77 D05.N1 208.63,37.77 213.71,37.77 D04.N2 214.98,37.77 220.06,37.77 D04.N1 221.33,37.77 226.41,37.77 D03.N2 227.68,37.77 232.76,37.77 D03.N1 234.03,37.77 239.11,37.77 D02.N2 240.38,37.77 245.46,37.77 D02.N1 246.73,37.77 251.81,37.77 D01.N2 253.08,37.77 258.16,37.77 D01.N1 258.48,38.72 257.21,39.99 257.21,56.82 | D15.T1 81.63,25.07 86.71,25.07 D14.T2 | D12.T2 112.11,25.07 107.03,25.07 D13.T1 | D12.T1 119.73,25.07 124.81,25.07 D11.T2 126.08,25.07 131.16,25.07 D11.T1 132.43,25.07 133.39,25.07 | 133.39,25.07 137.51,25.07 D10.T2 138.78,25.07 143.86,25.07 D10.T1 145.13,25.07 150.21,25.07 D09.T2 151.48,25.07 156.56,25.07 D09.T1 157.83,25.07 162.91,25.07 D08.T2 164.18,25.07 169.26,25.07 D08.T1 170.53,25.07 175.61,25.07 D07.T2 176.88,25.07 181.96,25.07 D07.T1 183.23,25.07 188.31,25.07 D06.T2 189.58,25.07 194.66,25.07 D06.T1 195.93,25.07 201.01,25.07 D05.T2 202.28,25.07 207.36,25.07 D05.T1 208.63,25.07 213.71,25.07 D04.T2 214.98,25.07 220.06,25.07 D04.T1 221.33,25.07 226.41,25.07 D03.T2 227.68,25.07 232.76,25.07 D03.T1 234.03,25.07 239.11,25.07 D02.T2 240.38,25.07 245.46,25.07 D02.T1 246.73,25.07 251.81,25.07 D01.T2 253.08,25.07 258.16,25.07 D01.T1
  Top 0.635: 133.39,37.77 133.39,25.07 | D12.F1 118.46,56.82 113.38,56.82 D12.F2 | D09.F2 151.48,56.82 156.56,56.82 D09.F1 157.83,56.82 162.91,56.82 D08.F2 164.18,56.82 169.26,56.82 D08.F1 170.53,56.82 175.61,56.82 D07.F2 176.88,56.82 181.96,56.82 D07.F1 183.23,56.82 188.31,56.82 D06.F2 189.58,56.82 194.66,56.82 D06.F1 195.93,56.82 201.01,56.82 D05.F2 202.28,56.82 207.36,56.82 D05.F1 208.63,56.82 213.71,56.82 D04.F2 214.98,56.82 220.06,56.82 D04.F1 221.33,56.82 226.41,56.82 D03.F2 227.68,56.82 232.76,56.82 D03.F1 234.03,56.82 239.11,56.82 D02.F2 240.38,56.82 245.46,56.82 D02.F1 246.73,56.82 251.81,56.82 D01.F2 253.08,56.82 257.21,56.82 | 257.21,56.82 258.16,56.82 D01.F1 258.48,57.77 257.21,59.04 257.21,66.35 | D11.C2 127.99,66.35 122.91,66.35 D12.C1 | D09.C1 161.01,66.35 166.09,66.35 D08.C2 167.36,66.35 172.44,66.35 D08.C1 173.71,66.35 178.79,66.35 D07.C2 180.06,66.35 185.14,66.35 D07.C1 186.41,66.35 191.49,66.35 D06.C2 192.76,66.35 197.84,66.35 D06.C1 199.11,66.35 204.19,66.35 D05.C2 205.46,66.35 210.54,66.35 D05.C1 211.81,66.35 216.89,66.35 D04.C2 218.16,66.35 223.24,66.35 D04.C1 224.51,66.35 229.59,66.35 D03.C2 230.86,66.35 235.94,66.35 D03.C1 237.21,66.35 242.29,66.35 D02.C2 243.56,66.35 248.64,66.35 D02.C1 | D02.C1 249.91,66.35 254.99,66.35 D01.C2 256.26,66.35 257.21,66.35 | 257.21,66.35 261.34,66.35 D01.C1 | C08.F1 170.53,126.67 175.61,126.67 C07.F2 176.88,126.67 181.96,126.67 C07.F1 183.23,126.67 188.31,126.67 C06.F2 189.58,126.67 194.66,126.67 C06.F1 195.93,126.67 201.01,126.67 C05.F2 202.28,126.67 207.36,126.67 C05.F1 208.63,126.67 213.71,126.67 C04.F2 214.98,126.67 220.06,126.67 C04.F1 221.33,126.67 226.41,126.67 C03.F2 227.68,126.67 232.76,126.67 C03.F1 234.03,126.67 239.11,126.67 C02.F2
  Top 0.635: C02.F1 246.73,126.67 251.81,126.67 C01.F2 253.08,126.67 258.16,126.67 C01.F1 258.48,127.62 257.21,128.89 257.21,136.2 | C08.C2 167.36,136.2 172.44,136.2 C08.C1 173.71,136.2 178.79,136.2 C07.C2 180.06,136.2 181.01,136.2 | 181.01,136.2 185.14,136.2 C07.C1 186.41,136.2 191.49,136.2 C06.C2 192.76,136.2 197.84,136.2 C06.C1 199.11,136.2 204.19,136.2 C05.C2 205.46,136.2 210.54,136.2 C05.C1 211.81,136.2 216.89,136.2 C04.C2 218.16,136.2 223.24,136.2 C04.C1 224.51,136.2 229.59,136.2 C03.C2 230.86,136.2 235.94,136.2 C03.C1 | C02.C2 243.56,136.2 248.64,136.2 C02.C1 249.91,136.2 254.99,136.2 C01.C2 256.26,136.2 257.21,136.2 | 257.21,136.2 261.34,136.2 C01.C1 | 171.49,107.62 170.53,107.62 C08.N1 | 171.49,107.62 175.61,107.62 C07.N2 176.88,107.62 181.96,107.62 C07.N1 183.23,107.62 188.31,107.62 C06.N2 189.58,107.62 194.66,107.62 C06.N1 195.93,107.62 201.01,107.62 C05.N2 202.28,107.62 207.36,107.62 C05.N1 208.63,107.62 213.71,107.62 C04.N2 214.98,107.62 220.06,107.62 C04.N1 221.33,107.62 226.41,107.62 C03.N2 227.68,107.62 232.76,107.62 C03.N1 234.03,107.62 239.11,107.62 C02.N2 | C02.N1 246.73,107.62 251.81,107.62 C01.N2 253.08,107.62 258.16,107.62 C01.N1 | B17.T1 B17.R1 | B18.T1 42.58,158.1 42.58,153.02 B18.V1 | B20.T1 17.18,158.1 17.18,153.02 B20.V1 17.18,151.75 17.18,141.59 14.64,139.05 14.64,137.15 C20.C2 | B19.T1 33.06,158.74 33.06,156.2 B19.U1 | C17.C2 52.11,135.88 52.11,130.8 C17.E2 52.74,129.53 53.06,129.21 53.06,126.03 55.28,123.81 55.28,121.27 C17.J1 55.28,120 55.28,117.46 54.01,116.19 54.01,113.02 52.74,111.75 C17.M2 52.74,110.48 54.01,109.21 54.01,100.95 55.28,99.68 55.28,95.87 C17.T1
  Top 0.635: 171.49,94.92 170.53,94.92 C08.T1 | 171.49,94.92 175.61,94.92 C07.T2 176.88,94.92 181.96,94.92 C07.T1 183.23,94.92 188.31,94.92 C06.T2 189.58,94.92 194.66,94.92 C06.T1 195.93,94.92 201.01,94.92 C05.T2 202.28,94.92 207.36,94.92 C05.T1 208.63,94.92 213.71,94.92 C04.T2 214.98,94.92 220.06,94.92 C04.T1 221.33,94.92 226.41,94.92 C03.T2 227.68,94.92 232.76,94.92 C03.T1 234.03,94.92 239.11,94.92 C02.T2 | 247.69,94.92 246.73,94.92 C02.T1 | 247.69,94.92 251.81,94.92 C01.T2 253.08,94.92 258.16,94.92 C01.T1 | 171.49,94.92 171.49,107.62 | 247.69,94.92 247.69,68.57 248.96,67.3 D02.C1 | 181.01,136.2 181.01,158.42 | 181.01,199.7 181.01,228.27
  Bottom 0.635: A14.N2 87.98,240.97 93.06,240.97 A14.N1 94.33,240.97 99.41,240.97 A13.N2 | A13.N1 107.03,240.97 112.11,240.97 A12.N2 113.38,240.97 118.46,240.97 A12.N1 | A11.N2 126.08,240.97 131.16,240.97 A11.N1 132.43,240.97 137.51,240.97 A10.N2 138.78,240.97 143.86,240.97 A10.N1 145.13,240.97 150.21,240.97 A09.N2 151.48,240.97 156.56,240.97 A09.N1 157.83,240.97 162.91,240.97 A08.N2 | A04.N1 220.06,240.97 214.98,240.97 A04.N2 | A03.N1 232.76,240.97 227.68,240.97 A03.N2 | A13.T2 99.41,228.27 94.33,228.27 A14.T1 93.06,228.27 87.98,228.27 A14.T2 86.71,228.27 81.63,228.27 A15.T1 80.36,228.9 80.05,229.22 76.24,229.22 70.84,234.62 68.93,234.62 A16.R1 | A13.T1 107.03,228.27 112.11,228.27 A12.T2 113.38,228.27 118.46,228.27 A12.T1 | A11.T2 126.08,228.27 131.16,228.27 A11.T1 132.43,228.27 137.51,228.27 A10.T2 138.78,228.27 143.86,228.27 A10.T1 145.13,228.27 150.21,228.27 A09.T2 151.48,228.27 156.56,228.27 A09.T1 157.83,228.27 162.91,228.27 A08.T2 | A04.T1 220.06,228.27 214.98,228.27 A04.T2 | A03.T1 232.76,228.27 227.68,228.27 A03.T2 | A13.F2 99.41,260.02 94.33,260.02 A14.F1 | A13.F1 107.03,260.02 112.11,260.02 A12.F2 113.38,260.02 118.46,260.02 A12.F1 | A11.F2 126.08,260.02 131.16,260.02 A11.F1 132.43,260.02 137.51,260.02 A10.F2 138.78,260.02 143.86,260.02 A10.F1 145.13,260.02 150.21,260.02 A09.F2 151.48,260.02 156.56,260.02 A09.F1 157.83,260.02 162.91,260.02 A08.F2 | A04.F1 220.06,260.02 214.98,260.02 A04.F2 | A03.F1 232.76,260.02 227.68,260.02 A03.F2 | A18N.C2 39.09,269.55 34.01,269.55 A19N.C1 | A16.R2 61.31,234.62 56.23,234.62 A17N.R1 | A16.N1 67.66,240.97 62.58,240.97 A16.N2
  Bottom 0.635: A16.F1 67.66,260.02 62.58,260.02 A16.F2 61.31,260.02 56.23,260.02 A17N.F1 | A19N.U2 27.66,225.73 29.88,227.95 A19N.T1 | A17N.R2 48.61,234.62 43.53,234.62 A18N.R1 | A18N.N2 37.18,240.97 42.26,240.97 A18N.N1 | A20N.K1 20.99,250.18 23.21,247.96 A19N.L2 | A19N.F2 24.48,260.02 29.56,260.02 A19N.F1 30.83,260.02 35.91,260.02 A18N.F2 | A20N.R2 11.78,234.62 16.86,234.62 A20N.R1 18.13,234.62 23.21,234.62 A19N.R2 | A20N.F1 16.86,260.02 11.78,260.02 A20N.F2 | A17N.N1 54.96,240.97 49.88,240.97 A17N.N2 | A13.C1 108.94,269.55 103.86,269.55 A13.C2 | A11.C2 129.26,269.55 134.34,269.55 A11.C1 135.61,269.55 140.69,269.55 A10.C2 141.96,269.55 147.04,269.55 A10.C1 148.31,269.55 153.39,269.55 A09.C2 | A04.C1 224.51,269.55 229.59,269.55 A03.C2 230.86,269.55 235.94,269.55 A03.C1 | A15.C2 78.46,270.18 79.73,271.45 87.98,271.45 89.25,270.18 89.89,270.18 A14.C2 | B14.N2 87.98,171.12 93.06,171.12 B14.N1 94.33,171.12 99.41,171.12 B13.N2 100.68,171.12 105.76,171.12 B13.N1 B12.N2 113.38,171.12 118.46,171.12 B12.N1 119.73,171.12 124.81,171.12 B11.N2 126.08,171.12 131.16,171.12 B11.N1 132.43,171.12 137.51,171.12 B10.N2 138.78,171.12 143.86,171.12 B10.N1 145.13,171.12 150.21,171.12 B09.N2 151.48,171.12 156.56,171.12 B09.N1 157.83,171.12 162.91,171.12 B08.N2 | B06.N2 188.31,171.12 183.23,171.12 B07.N1 | B01.N2 251.81,171.12 246.73,171.12 B02.N1 | B16.T1 68.93,158.42 70.2,157.15 76.24,157.15 77.51,158.42 80.36,158.42 B15.T1 81.63,158.42 86.71,158.42 B14.T2 87.98,158.42 93.06,158.42 B14.T1 94.33,158.42 99.41,158.42 B13.T2 100.68,158.42 105.76,158.42 B13.T1 107.03,158.42 112.11,158.42 B12.T2 113.38,158.42 118.46,158.42 B12.T1 119.73,158.42 124.81,158.42 B11.T2 126.08,158.42 131.16,158.42 B11.T1 132.43,158.42 137.51,158.42 B10.T2 138.78,158.42 143.86,158.42 B10.T1 145.13,158.42 150.21,158.42 B09.T2 151.48,158.42 156.56,158.42 B09.T1 157.83,158.42 162.91,158.42 B08.T2
  Bottom 0.635: B07.T2 175.61,158.42 170.53,158.42 B08.T1 | B01.T2 251.81,158.42 246.73,158.42 B02.T1 | B14.F2 87.98,190.17 93.06,190.17 B14.F1 | B13.F2 100.68,190.17 105.76,190.17 B13.F1 B12.F2 113.38,190.17 118.46,190.17 B12.F1 119.73,190.17 124.81,190.17 B11.F2 126.08,190.17 131.16,190.17 B11.F1 132.43,190.17 137.51,190.17 B10.F2 138.78,190.17 143.86,190.17 B10.F1 145.13,190.17 150.21,190.17 B09.F2 151.48,190.17 156.56,190.17 B09.F1 157.83,190.17 162.91,190.17 B08.F2 | B05.F1 207.36,190.17 202.28,190.17 B05.F2 | B01.F2 251.81,190.17 246.73,190.17 B02.F1 | B20.C2 14.96,199.7 16.23,198.43 24.8,198.43 26.07,199.7 26.39,199.7 B19.C2 27.66,200.33 28.93,201.6 37.82,201.6 39.09,200.33 B18.C2 40.36,199.7 41.63,198.43 50.52,198.43 51.79,199.7 B17.C2 53.06,199.7 55.6,199.7 56.87,198.43 59.41,198.43 60.36,199.38 64.17,199.38 64.49,199.7 B16.C2 65.76,199.7 69.57,199.7 70.84,198.43 72.11,198.43 72.43,198.74 76.24,198.74 77.19,199.7 B15.C2 78.46,199.7 79.41,198.74 83.22,198.74 83.54,198.43 84.81,198.43 85.76,199.38 90.21,199.38 B14.C2 91.16,199.7 96.24,199.7 B14.C1 97.51,199.7 102.59,199.7 B13.C2 | B13.C1 110.21,199.7 115.29,199.7 B12.C2 116.56,199.7 121.64,199.7 B12.C1 122.91,199.7 127.99,199.7 B11.C2 129.26,199.7 134.34,199.7 B11.C1 135.61,199.7 140.69,199.7 B10.C2 141.96,199.7 147.04,199.7 B10.C1 148.31,199.7 153.39,199.7 B09.C2 154.66,199.7 159.74,199.7 B09.C1 161.01,199.7 166.09,199.7 B08.C2 | B04.C2 216.89,199.7 211.81,199.7 B05.C1 | B01.C2 254.99,199.7 249.91,199.7 B02.C1 | D14.N2 87.98,37.77 93.06,37.77 D14.N1 | D13.N2 100.68,37.77 105.76,37.77 D13.N1 107.03,37.77 112.11,37.77 D12.N2 113.38,37.77 118.46,37.77 D12.N1 119.73,37.77 124.81,37.77 D11.N2 126.08,37.77 131.16,37.77 D11.N1
  Bottom 0.635: 53.85,23.96 54.96,25.07 D17.T1 | 53.85,23.96 53.69,23.8 44.8,23.8 43.53,25.07 D18.T1 | 53.85,23.96 54.01,23.8 62.58,23.8 62.9,24.12 66.71,24.12 67.66,25.07 D16.T1 68.93,25.07 69.89,24.12 73.7,24.12 74.01,23.8 79.09,23.8 80.36,25.07 D15.T1 | D14.T2 87.98,25.07 93.06,25.07 D14.T1 94.33,25.07 99.41,25.07 D13.T2 100.68,25.07 105.76,25.07 D13.T1 | D12.T1 118.46,25.07 113.38,25.07 D12.T2 | D14.F2 87.98,56.82 93.06,56.82 D14.F1 94.33,56.82 99.41,56.82 D13.F2 100.68,56.82 105.76,56.82 D13.F1 107.03,56.82 112.11,56.82 D12.F2 | D12.F1 119.73,56.82 124.81,56.82 D11.F2 126.08,56.82 131.16,56.82 D11.F1 132.43,56.82 137.51,56.82 D10.F2 138.78,56.82 143.86,56.82 D10.F1 145.13,56.82 150.21,56.82 D09.F2 | D19.F1 30.52,57.77 30.52,61.9 32.1,61.9 36.87,66.66 D18.C2 40.36,66.35 41.63,65.08 50.52,65.08 50.68,65.23 | 50.68,65.23 51.79,66.35 D17.C2 | 50.68,65.23 50.84,65.08 59.41,65.08 61,66.66 D16.C2 65.76,66.35 66.71,65.39 70.52,65.39 70.84,65.08 73.38,65.08 74.65,66.35 77.19,66.35 D15.C2 78.46,66.35 79.41,65.39 83.22,65.39 83.54,65.08 86.08,65.08 87.35,66.35 89.89,66.35 D14.C2 91.16,66.35 96.24,66.35 D14.C1 97.51,66.35 102.59,66.35 D13.C2 103.86,66.35 108.94,66.35 D13.C1 110.21,66.35 115.29,66.35 D12.C2 116.56,66.35 121.64,66.35 D12.C1 | D11.C2 129.26,66.35 134.34,66.35 D11.C1 135.61,66.35 140.69,66.35 D10.C2 141.96,66.35 147.04,66.35 D10.C1 148.31,66.35 153.39,66.35 D09.C2 154.66,66.35 159.74,66.35 D09.C1 | C14.F2 87.98,126.67 93.06,126.67 C14.F1 94.33,126.67 99.41,126.67 C13.F2 100.68,126.67 105.76,126.67 C13.F1 107.03,126.67 112.11,126.67 C12.F2 113.38,126.67 118.46,126.67 C12.F1 C11.F2 126.08,126.67 131.16,126.67 C11.F1 132.43,126.67 137.51,126.67 C10.F2 138.78,126.67 143.86,126.67 C10.F1 145.13,126.67 150.21,126.67 C09.F2 151.48,126.67 156.56,126.67 C09.F1 157.83,126.67 162.91,126.67 C08.F2 164.18,126.67 169.26,126.67 C08.F1
  Bottom 0.635: C02.F1 245.46,126.67 240.38,126.67 C02.F2 | C08.C2 166.09,136.2 161.01,136.2 C09.C1 159.74,136.2 154.66,136.2 C09.C2 153.39,136.2 148.31,136.2 C10.C1 147.04,136.2 141.96,136.2 C10.C2 140.69,136.2 135.61,136.2 C11.C1 134.34,136.2 129.26,136.2 C11.C2 127.99,136.2 122.91,136.2 C12.C1 121.64,136.2 116.56,136.2 C12.C2 115.29,136.2 110.21,136.2 C13.C1 108.94,136.2 103.86,136.2 C13.C2 102.59,136.2 97.51,136.2 C14.C1 96.24,136.2 91.16,136.2 C14.C2 89.89,136.83 89.25,136.83 87.98,138.1 79.73,138.1 78.46,136.83 C15.C2 77.19,136.2 75.92,134.93 70.52,134.93 69.25,136.2 65.76,136.2 C16.C2 C17.C1 58.14,136.2 53.06,136.2 C17.C2 51.79,136.2 49.25,136.2 47.98,134.93 41.63,134.93 40.36,136.2 C18.C2 39.09,136.2 37.82,134.93 25.44,134.93 25.28,135.08 | C02.C2 242.29,136.2 237.21,136.2 C03.C1 | C14.N2 C14.N1 94.33,107.62 99.41,107.62 C13.N2 100.68,107.62 105.76,107.62 C13.N1 107.03,107.62 112.11,107.62 C12.N2 C12.N1 119.73,107.62 124.81,107.62 C11.N2 126.08,107.62 131.16,107.62 C11.N1 132.43,107.62 137.51,107.62 C10.N2 138.78,107.62 143.86,107.62 C10.N1 145.13,107.62 150.21,107.62 C09.N2 151.48,107.62 156.56,107.62 C09.N1 157.83,107.62 162.91,107.62 C08.N2 164.18,107.62 169.26,107.62 C08.N1 | C02.N1 245.46,107.62 240.38,107.62 C02.N2 | B17.P1 58.46,167.63 56.23,165.4 B17.R1 | B18.U1 45.76,154.93 43.53,152.71 B18.V1 42.26,152.71 40.99,153.98 32.42,153.98 32.26,154.13 | B20.V1 18.13,152.71 20.36,154.93 B20.U1 21.31,155.24 22.58,153.98 25.12,153.98 26.39,152.71 29.56,152.71 B19.V1 30.83,152.71 32.26,154.13 | 32.26,154.13 33.06,154.93 B19.U1
  Bottom 0.635: B17.T1 54.96,159.05 54.01,160.01 50.2,160.01 49.88,160.33 47.34,160.33 46.07,159.05 43.53,159.05 B18.T1 | 25.28,135.08 26.39,136.2 C19.C2 | 25.28,135.08 25.12,134.93 16.23,134.93 14.96,136.2 C20.C2 | C17.P1 58.46,105.4 58.46,109.52 54.65,109.52 53.38,110.8 53.06,110.8 C17.M2 | C20.T1 18.13,95.55 19.4,96.83 28.29,96.83 29.56,95.55 C19.T1 30.83,94.92 32.1,93.65 40.99,93.65 42.26,94.92 C18.T1 43.53,94.92 48.61,94.92 C17.T2 49.88,94.92 54.96,94.92 C17.T1 56.23,94.92 57.19,93.97 61,93.97 61.31,93.65 63.85,93.65 65.12,94.92 67.66,94.92 C16.T1 68.93,94.92 69.89,93.97 73.7,93.97 74.01,93.65 76.55,93.65 77.82,94.92 80.36,94.92 C15.T1 81.63,94.92 86.71,94.92 C14.T2 87.98,94.92 93.06,94.92 C14.T1 94.33,94.92 99.41,94.92 C13.T2 100.68,94.92 105.76,94.92 C13.T1 107.03,94.92 112.11,94.92 C12.T2 113.38,94.92 118.46,94.92 C12.T1 119.73,94.92 124.81,94.92 C11.T2 126.08,94.92 131.16,94.92 C11.T1 132.43,94.92 137.51,94.92 C10.T2 138.78,94.92 143.86,94.92 C10.T1 145.13,94.92 150.21,94.92 C09.T2 151.48,94.92 156.56,94.92 C09.T1 157.83,94.92 162.91,94.92 C08.T2 164.18,94.92 169.26,94.92 C08.T1 | C02.T1 245.46,94.92 240.38,94.92 C02.T2
N$1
